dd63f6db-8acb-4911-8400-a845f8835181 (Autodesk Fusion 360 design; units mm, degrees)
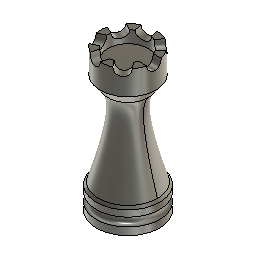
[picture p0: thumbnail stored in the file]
sketch "Sketch1" plane through (0, 0, 0) normal (0, 1, 0) x axis (1, 0, 0)
  line L1 (10, 0) -> (0, 0)
  line L2 (0, -45) -> (0, 0)
  line L3 (10, -2.3451) -> (10, 0)
  line L4 (10, -7.0651) -> (10, -5.0722)
  line L5 (9.3312, -7.8086) -> (10, -7.0651)
  line L6 (6.3819, -41.154) -> (0, -41.154)
  line L7 (6.3819, -45) -> (6.3819, -41.154)
  line L8 (8.7944, -45) -> (6.3819, -45)
  line L9 (8.7944, -37.2731) -> (8.7944, -45)
  line L10 (6.3819, -34.0215) -> (8.7944, -37.2731)
  curve K1 (9.3312, -7.8086) -> (6.3819, -34.0215)
  arc A1 centre (9.7587, -3.7087) radius 1.3847 clockwise from (10, -5.0722) to (10, -2.3451)
  point P1 (0, 0)
  point P2 (0, 0)
  point P4 (0, 0)
  point P11 (0, -41.154)
  point P3 (10, 0)
  point P5 (0, -45)
  point P9 (10, -7.0651)
  point P10 (9.3312, -7.8086)
  coincident P1 P2
  horizontal L1
  coincident P1 P4
  perpendicular L1 L2
  perpendicular L1 L3
  vertical L4
  coincident L2 P11
  perpendicular L2 L6
  perpendicular L6 L7
  perpendicular L7 L8
  perpendicular L8 L9
  dimension "d1" distance P2 P3 = 10
  dimension "d2" distance P4 P5 = 45
  dimension "d3" distance P9 P10 = 1
revolve "Revolve1" sketch "Sketch1" AlongAngle 360
work_plane "WorkPlane1" AlongDistance 10.119
sketch "Sketch2" plane through (10.119, 0, 0) normal (1, 0, 0) x axis (0, 1, 0)
  circle C1 centre (-0.268, 44.9839) radius 2.2012
extrude "Extrude1" cut sketch "Sketch2" against normal blind 5.886
circular_pattern "C-Pattern1" TotalAngle 360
